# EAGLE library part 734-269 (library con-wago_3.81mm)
Serie 734, Stiftleiste (für Leiterplatten) Einlötstift abgewinkelt 1 x 1 mm / Series 734, Male header (for PCBs) Angled solder pin 1 x 1 mm Polzahl / Pole No.: 9 Rastermaß / Pitch: 3.81 mm Bemessungsspannung / Rated Voltage: 160 V Nennstrom / Nominal Current: 10 A Lötstiftlänge: / Solder Pin Length: 3.8 mm Farbe / Color: orange / orange Stand: 01.01.2012. Die jeweils aktuellen Daten zu diesem Artikel finden Sie in unserem Produktkatalog, den Sie unter www.wago.com einsehen können. As of: 01/01/2012. Please find the newest data for this article in our product catalogue, which can be viewed under www.wago.com.
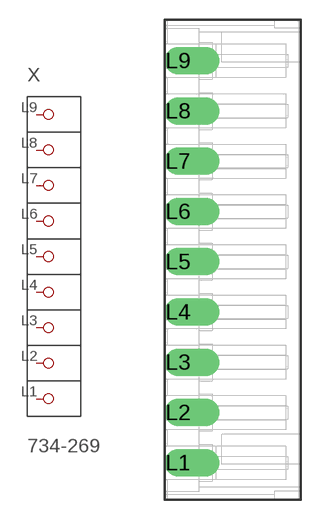
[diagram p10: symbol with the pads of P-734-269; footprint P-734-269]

Designator prefix X

## 734-269  [P-734-269]
L1  P1
L2  P2
L3  P3
L4  P4
L5  P5
L6  P6
L7  P7
L8  P8
L9  P9

## Footprint P-734-269 (pad centres in mm)
drill 1.4 pad 2 offset: L1 -4.15,-15.39; L2 -4.15,-11.58; L3 -4.15,-7.77; L4 -4.15,-3.96; L5 -4.15,-0.15; L6 -4.15,3.66; L7 -4.15,7.47; L8 -4.15,11.28; L9 -4.15,15.09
